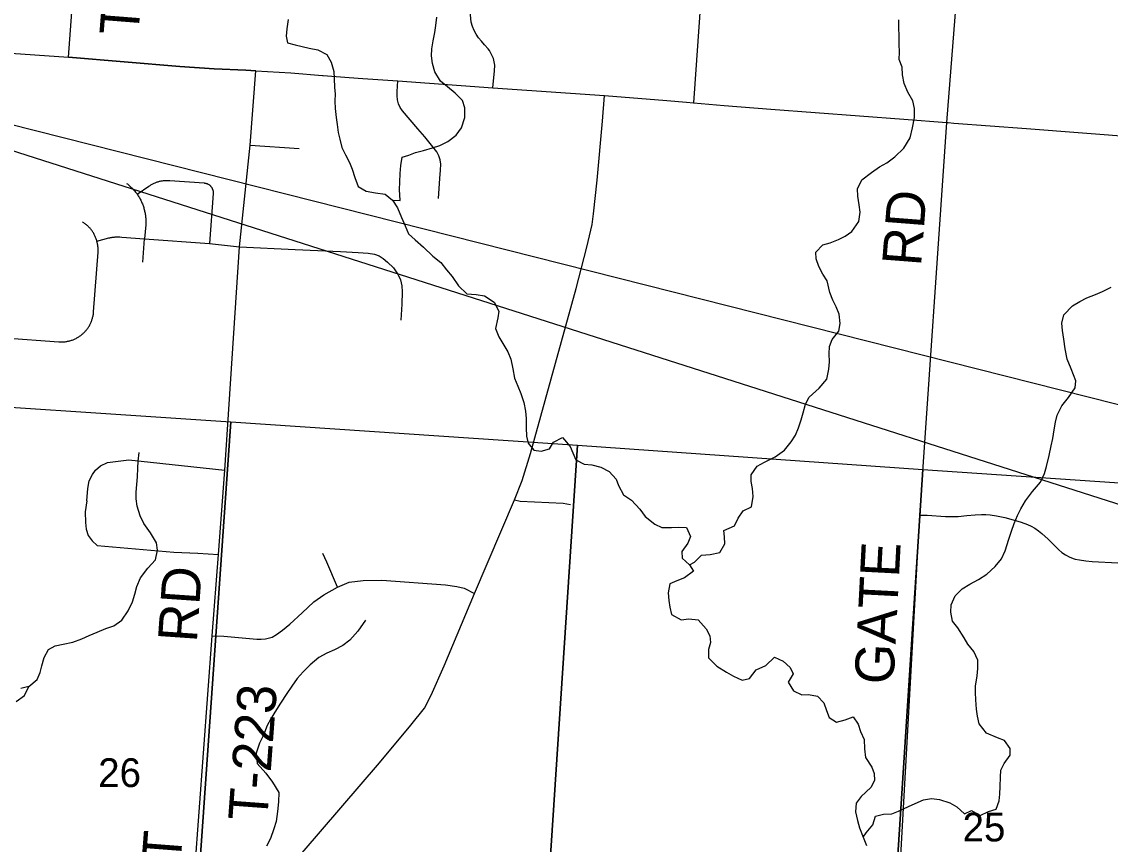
# Model space of a CAD drawing. Extents: x 0 to 34, y 0 to 22.
# Drawn here: x 6.46 to 8.044, y 16.406 to 17.603 of the extents above; entities that cross this region are included whole.
import ezdxf

# ---------------------------------------------------------------- set-up
doc = ezdxf.new("R2010")
doc.units = 0
for name, color, linetype in [('GM_X_Corporation', 7, 'Continuous'), ('GM_X_County_Road', 7, 'Continuous'), ('GM_X_Minor_Lake', 7, 'Continuous'), ('GM_X_Minor_River', 7, 'Continuous'), ('GM_X_Section_Text', 7, 'Continuous'), ('GM_X_State_Route', 7, 'Continuous'), ('GM_X_Township_Road', 7, 'Continuous'), ('GM_X_Township_Road_Text', 7, 'Continuous'), ('SH_Text', 7, 'Continuous')]:
    doc.layers.add(name, color=color, linetype=linetype)

msp = doc.modelspace()

# ---------------------------------------------------------------- linework, layer by layer
at = {"layer": 'GM_X_Corporation'}
for points in [[(6.2535, 17.0548), (6.7642, 17.0207), (6.6929, 16.0021), (6.1806, 16.0412)], [(6.7642, 17.0207), (7.2687, 16.9868), (7.2018, 15.9686), (6.6929, 16.0021)], [(7.2687, 16.9868), (7.7715, 16.9516), (7.7055, 15.9334), (7.2018, 15.9686)], [(7.7715, 16.9516), (8.2797, 16.9169), (8.2166, 15.8976), (7.7055, 15.9334)]]:
    msp.add_lwpolyline(points, close=True, dxfattribs=at)
at = {"layer": 'GM_X_County_Road'}
msp.add_lwpolyline([(6.556, 16.0261), (6.6991, 16.1965), (6.9804, 16.5242), (7.026, 16.579), (7.046, 16.6041), (7.0557, 16.6231), (7.0747, 16.6658), (7.119, 16.7711), (7.177, 16.9074), (7.1885, 16.9354), (7.2006, 16.9746), (7.2668, 17.2151), (7.2825, 17.2751), (7.2901, 17.3083), (7.2922, 17.3236), (7.2973, 17.373), (7.3052, 17.4586), (7.3081, 17.496)], dxfattribs=at)
at = {"layer": 'GM_X_Minor_Lake'}
msp.add_lwpolyline([(6.4518, 16.6138), (6.464, 16.6224), (6.4702, 16.6353), (6.4585, 16.6328)], dxfattribs=at)
at = {"layer": 'GM_X_Minor_River'}
for points in [[(6.8478, 17.6065), (6.8458, 17.5929), (6.8449, 17.5823), (6.8467, 17.5727), (6.858, 17.57), (6.8678, 17.5676), (6.878, 17.5648), (6.8909, 17.5624), (6.9037, 17.5558), (6.9104, 17.5447), (6.914, 17.531), (6.9147, 17.5208), (6.9153, 17.5079), (6.9159, 17.4984), (6.9158, 17.4877), (6.9161, 17.4771), (6.9175, 17.4642), (6.9189, 17.4539), (6.9206, 17.4421), (6.9228, 17.4323), (6.9257, 17.4205), (6.9313, 17.4098), (6.9368, 17.3983), (6.9409, 17.3888), (6.9449, 17.3766), (6.9497, 17.3636), (6.9614, 17.3567), (6.975, 17.3543), (6.9886, 17.3522), (6.9995, 17.3434), (7.0066, 17.3323), (7.0125, 17.3182), (7.018, 17.3064), (7.0228, 17.2946), (7.0326, 17.2861), (7.0446, 17.2753), (7.0581, 17.2623), (7.0697, 17.2527), (7.0783, 17.242), (7.0862, 17.2324), (7.0955, 17.219), (7.1079, 17.2071), (7.1211, 17.2062), (7.1332, 17.2042), (7.1475, 17.1953), (7.1542, 17.182), (7.153, 17.1725), (7.1494, 17.157), (7.1542, 17.1448), (7.1616, 17.1325), (7.1676, 17.1226), (7.1716, 17.1119), (7.1745, 17.0979), (7.177, 17.0846), (7.1818, 17.0727), (7.1863, 17.0621), (7.1907, 17.0491), (7.1932, 17.0362), (7.1942, 17.0259), (7.1941, 17.0119), (7.1947, 17.0001), (7.1968, 16.9898), (7.2054, 16.9795)], [(6.9995, 17.3434), (7.0105, 17.3433), (7.0099, 17.3592), (7.01, 17.3698), (7.0105, 17.3824), (7.0114, 17.3941), (7.0134, 17.4063), (7.0233, 17.4092), (7.0328, 17.4129), (7.0446, 17.4162), (7.0575, 17.4198), (7.0682, 17.4231), (7.08, 17.4291), (7.0922, 17.4381), (7.0999, 17.449), (7.105, 17.4641), (7.1048, 17.4782), (7.1015, 17.4889), (7.0906, 17.4996), (7.0797, 17.5088), (7.0692, 17.5169), (7.061, 17.5307), (7.0577, 17.5425), (7.0563, 17.5539), (7.0568, 17.5641), (7.0588, 17.5755), (7.0609, 17.588), (7.0625, 17.5982), (7.0641, 17.6103)], [(7.4321, 16.8128), (7.4393, 16.8165), (7.4493, 16.8267), (7.4618, 16.8277), (7.4758, 16.8306), (7.4832, 16.843), (7.4829, 16.8533), (7.4819, 16.8628), (7.4975, 16.8694), (7.5025, 16.8804), (7.5102, 16.8913), (7.522, 16.8973), (7.5244, 16.912), (7.5234, 16.9238), (7.5216, 16.9341), (7.5218, 16.9439), (7.5302, 16.9564), (7.5409, 16.9623), (7.5565, 16.9698), (7.5702, 16.9795), (7.5798, 16.9919), (7.586, 17.0017), (7.5903, 17.0123), (7.5942, 17.0237), (7.5973, 17.0339), (7.6005, 17.0464), (7.6063, 17.0569), (7.6205, 17.0697), (7.6316, 17.0829), (7.6348, 17.0976), (7.6357, 17.1083), (7.6354, 17.1197), (7.6355, 17.1307), (7.6394, 17.1409), (7.6494, 17.1529), (7.6514, 17.1639), (7.6497, 17.1776), (7.6452, 17.1883), (7.6404, 17.1978), (7.636, 17.2092), (7.6324, 17.226), (7.626, 17.2359), (7.6201, 17.247), (7.6164, 17.258), (7.6158, 17.2679), (7.6258, 17.2788), (7.6364, 17.2813), (7.6489, 17.2865), (7.6585, 17.291), (7.668, 17.2981), (7.6784, 17.3124), (7.6804, 17.3261), (7.6787, 17.3367), (7.6769, 17.3493), (7.6766, 17.3603), (7.6828, 17.3731), (7.6966, 17.384), (7.7084, 17.3922), (7.7191, 17.3978), (7.7309, 17.4068), (7.7439, 17.4195), (7.7532, 17.4346), (7.7564, 17.449), (7.7592, 17.4642), (7.7593, 17.4771), (7.7568, 17.4881), (7.7497, 17.5011), (7.7442, 17.5133), (7.7417, 17.5262), (7.7414, 17.5373), (7.737, 17.5483), (7.7375, 17.5593), (7.7372, 17.5707), (7.737, 17.5836), (7.7364, 17.5939), (7.7365, 17.6064)], [(7.6846, 16.4162), (7.6892, 16.4222), (7.6988, 16.4343), (7.7024, 16.4467), (7.7142, 16.4497), (7.7263, 16.4499), (7.7362, 16.454), (7.7506, 16.4607), (7.7602, 16.4651), (7.7727, 16.4707), (7.7841, 16.4725), (7.7958, 16.4708), (7.8109, 16.4661), (7.8211, 16.4603), (7.8324, 16.4503), (7.8423, 16.4548), (7.8551, 16.4478), (7.8669, 16.4534), (7.8783, 16.4571), (7.8826, 16.4692), (7.8838, 16.4786), (7.8843, 16.49), (7.8845, 16.5037), (7.8849, 16.5136), (7.89, 16.5234), (7.8988, 16.5354), (7.8985, 16.5453), (7.8903, 16.5571), (7.8801, 16.5607), (7.8643, 16.5677), (7.8535, 16.5811), (7.8509, 16.5921), (7.8495, 16.6027), (7.8485, 16.616), (7.8483, 16.6267), (7.8484, 16.6361), (7.8504, 16.6509), (7.8517, 16.6615), (7.8518, 16.6737), (7.8459, 16.6867), (7.8369, 16.697), (7.8317, 16.7065), (7.8224, 16.7207), (7.8149, 16.7306), (7.8124, 16.7436), (7.8129, 16.7546), (7.8184, 16.7674), (7.8287, 16.7779), (7.8401, 16.7843), (7.8527, 16.7913), (7.8645, 16.7992), (7.8768, 16.8104), (7.886, 16.8214), (7.8914, 16.8331), (7.8965, 16.8501), (7.9004, 16.8618), (7.9043, 16.8728), (7.9094, 16.8845), (7.914, 16.8943), (7.921, 16.906), (7.931, 16.9192), (7.9429, 16.9331), (7.9487, 16.9456), (7.9518, 16.9558), (7.9554, 16.9717), (7.9586, 16.9861), (7.961, 16.9967), (7.9626, 17.0092), (7.9647, 17.0202), (7.967, 17.0304), (7.974, 17.0444), (7.9836, 17.0561), (7.9932, 17.0704), (7.9941, 17.0806), (7.9875, 17.0982), (7.9816, 17.1123), (7.9787, 17.1271), (7.9766, 17.1412), (7.9748, 17.1541), (7.9738, 17.1643), (7.9769, 17.1765), (7.9892, 17.1896), (7.9999, 17.196), (8.0102, 17.2012), (8.0227, 17.2064), (8.033, 17.2108), (8.0456, 17.2171)], [(7.2054, 16.9795), (7.216, 16.9782), (7.2282, 16.9815), (7.234, 16.9913), (7.2469, 16.998), (7.2582, 16.985), (7.2618, 16.9755), (7.2663, 16.9656), (7.2787, 16.9594), (7.2897, 16.9581), (7.3029, 16.9549), (7.315, 16.9484), (7.3251, 16.9376), (7.3284, 16.9281), (7.3358, 16.9148), (7.3475, 16.9067), (7.3595, 16.8936), (7.3673, 16.8829), (7.3816, 16.8718), (7.3917, 16.8671), (7.4058, 16.867), (7.4156, 16.8676), (7.4277, 16.8671), (7.4333, 16.8541), (7.4294, 16.8443), (7.4205, 16.8319), (7.4212, 16.8224), (7.4321, 16.8128), (7.4377, 16.8032), (7.4247, 16.7939), (7.4133, 16.7895), (7.4034, 16.785), (7.4009, 16.7717), (7.4016, 16.7607), (7.403, 16.7512), (7.4059, 16.7402), (7.4198, 16.7328), (7.4308, 16.7342), (7.4445, 16.7326), (7.4561, 16.7195), (7.4613, 16.7092), (7.4623, 16.6997), (7.4595, 16.6895), (7.4594, 16.6774), (7.4718, 16.6651), (7.4857, 16.6562), (7.4959, 16.6504), (7.5083, 16.6446), (7.5193, 16.6472), (7.5289, 16.6596), (7.543, 16.6663), (7.5556, 16.6783), (7.5684, 16.6725), (7.5782, 16.6632), (7.5826, 16.6537), (7.5753, 16.642), (7.5835, 16.6294), (7.5956, 16.6236), (7.605, 16.6239), (7.6183, 16.6215), (7.6276, 16.6115), (7.6313, 16.6004), (7.6354, 16.5902), (7.6459, 16.5836), (7.6584, 16.5869), (7.6702, 16.5913), (7.6773, 16.5806), (7.681, 16.5699), (7.6862, 16.5585), (7.6864, 16.5445), (7.6882, 16.5323), (7.6975, 16.5182), (7.7008, 16.5086), (7.7014, 16.4984), (7.696, 16.4882), (7.6819, 16.4754), (7.6746, 16.4656), (7.6737, 16.4531), (7.6762, 16.4402), (7.6795, 16.4295), (7.6846, 16.4162), (7.6894, 16.404)], [(6.4702, 16.6353), (6.4821, 16.6458), (6.4864, 16.656), (6.4891, 16.6658), (6.4923, 16.6779), (6.4985, 16.6896), (6.5084, 16.6949), (6.5202, 16.697), (6.5342, 16.6999), (6.5471, 16.7051), (6.5578, 16.7099), (6.5696, 16.7147), (6.5821, 16.7199), (6.5936, 16.724), (6.6054, 16.7322), (6.6146, 16.7458), (6.6208, 16.759), (6.6244, 16.7699), (6.6271, 16.7813), (6.6329, 16.7938), (6.6433, 16.8077), (6.6544, 16.8201), (6.6572, 16.8341), (6.6558, 16.8448), (6.6473, 16.8593), (6.6376, 16.873), (6.6324, 16.8841), (6.6276, 16.8982), (6.6262, 16.9088), (6.6263, 16.9187), (6.6272, 16.9297), (6.6281, 16.9407), (6.6286, 16.9532), (6.6295, 16.9635), (6.6307, 16.9764)], [(6.96, 16.7319), (6.9488, 16.7161), (6.9373, 16.7029), (6.9274, 16.6951), (6.9152, 16.6891), (6.9041, 16.6839), (6.8923, 16.6776), (6.8797, 16.6671), (6.8697, 16.6569), (6.8609, 16.6472), (6.8529, 16.6359), (6.8455, 16.6253), (6.8367, 16.6114), (6.8282, 16.5982), (6.8224, 16.5884), (6.817, 16.5785), (6.8119, 16.5646), (6.8061, 16.5528), (6.801, 16.5385), (6.8024, 16.5233), (6.8151, 16.5091), (6.8248, 16.4961), (6.8338, 16.4812), (6.8336, 16.4675), (6.8323, 16.4535), (6.8303, 16.4391), (6.8267, 16.4281), (6.8217, 16.4142), (6.8159, 16.4032)]]:
    msp.add_lwpolyline(points, dxfattribs=at)
at = {"layer": 'GM_X_State_Route'}
for p, q in [((6.8986, 17.5251), (6.9365, 17.5223)), ((7.7438, 17.4615), (7.8067, 17.4568)), ((7.8067, 17.4568), (7.8086, 17.4566)), ((7.8086, 17.4566), (7.8165, 17.456))]:
    msp.add_line(p, q, dxfattribs=at)
for points in [[(5.9774, 17.5906), (5.9905, 17.5897), (6.0278, 17.587), (6.0741, 17.5836), (6.1651, 17.5775), (6.2475, 17.5714), (6.528, 17.552)], [(6.528, 17.552), (6.6901, 17.5382), (6.7397, 17.5351), (6.7862, 17.5328), (6.8004, 17.5319)], [(6.8004, 17.5319), (6.8513, 17.5289), (6.8976, 17.5252), (6.8986, 17.5251)], [(6.9365, 17.5223), (6.9565, 17.5209), (7.0075, 17.5176), (7.1456, 17.5072), (7.3081, 17.496)], [(7.3081, 17.496), (7.3987, 17.4886), (7.4277, 17.4861)], [(7.4277, 17.4861), (7.4377, 17.4852), (7.4823, 17.4816), (7.5504, 17.4761), (7.7438, 17.4615)], [(7.8165, 17.456), (7.9224, 17.4479), (8.1671, 17.4291), (8.3155, 17.4173), (8.4063, 17.4124), (8.5807, 17.4058), (8.7608, 17.3992), (8.8999, 17.39), (8.9, 17.39)]]:
    msp.add_lwpolyline(points, dxfattribs=at)
at = {"layer": 'GM_X_Township_Road'}
for p, q in [((6.7924, 17.4238), (6.8637, 17.4188)), ((6.6362, 17.2535), (6.6387, 17.2875))]:
    msp.add_line(p, q, dxfattribs=at)
for points in [[(6.528, 17.552), (6.5428, 17.755), (6.553, 17.872), (6.5547, 17.9434), (6.5622, 17.9715), (6.5676, 18.0635)], [(7.8067, 17.4568), (7.8439, 17.9308), (7.8449, 17.9659)], [(7.1387, 17.564), (7.1336, 17.5698), (7.1289, 17.5751), (7.1249, 17.58), (7.1213, 17.5852), (7.1184, 17.5908), (7.116, 17.5967), (7.1142, 17.6027), (7.1133, 17.6084), (7.1131, 17.6136), (7.1135, 17.6217), (7.1141, 17.6322), (7.1163, 17.662), (7.1202, 17.7086), (7.1252, 17.7731)], [(7.4527, 17.6997), (7.4377, 17.4852)], [(7.1456, 17.5072), (7.1482, 17.5322), (7.1484, 17.5401), (7.1463, 17.5499), (7.1406, 17.5618), (7.1387, 17.564)], [(6.8004, 17.5319), (6.7862, 17.5328), (6.7397, 17.5351), (6.6901, 17.5382), (6.528, 17.552)], [(6.6991, 16.1965), (6.737, 16.7093), (6.7461, 16.8276), (6.7553, 16.9507), (6.7768, 17.2757), (6.7924, 17.4238), (6.8004, 17.5319)], [(7.0667, 17.3463), (7.0686, 17.3752), (7.0695, 17.3871), (7.0697, 17.396), (7.0689, 17.4023), (7.067, 17.4083), (7.0656, 17.4112), (7.0641, 17.414), (7.0604, 17.4191), (7.0464, 17.4358), (7.0362, 17.4475), (7.0143, 17.4735), (7.0107, 17.4785), (7.008, 17.4838), (7.0066, 17.4896), (7.0062, 17.4957), (7.0063, 17.5019), (7.0075, 17.5176)], [(7.5902, 15.9401), (7.5965, 15.9796), (7.6036, 16.0079), (7.6181, 16.0362), (7.6409, 16.0588), (7.6848, 16.0992), (7.706, 16.125), (7.7171, 16.1497), (7.7242, 16.1769), (7.7323, 16.2582), (7.7673, 16.885), (7.8067, 17.4568)], [(6.6124, 17.3681), (6.6135, 17.3673), (6.6146, 17.3664), (6.6157, 17.3655), (6.6168, 17.3646), (6.6178, 17.3637), (6.6188, 17.3627), (6.6198, 17.3618), (6.6208, 17.3608), (6.6218, 17.3598), (6.6227, 17.3587), (6.6236, 17.3577), (6.6245, 17.3566), (6.6254, 17.3555), (6.6262, 17.3544), (6.6271, 17.3533), (6.6279, 17.3522), (6.6287, 17.351), (6.6295, 17.3498), (6.6302, 17.3486), (6.631, 17.3474), (6.6317, 17.3461), (6.6323, 17.3449), (6.633, 17.3436), (6.6336, 17.3423), (6.6342, 17.341), (6.6348, 17.3397), (6.6354, 17.3384), (6.6359, 17.337), (6.6364, 17.3357), (6.6368, 17.3343), (6.6373, 17.333), (6.6377, 17.3316), (6.6381, 17.3302), (6.6384, 17.3288), (6.6387, 17.3274), (6.639, 17.326), (6.6393, 17.3246), (6.6395, 17.3232), (6.6397, 17.3218), (6.6399, 17.3204), (6.64, 17.319), (6.6402, 17.3175), (6.6402, 17.3161), (6.6403, 17.3147), (6.6403, 17.3132), (6.6403, 17.3118), (6.6403, 17.3104), (6.6402, 17.309), (6.6402, 17.3075), (6.6387, 17.2875)], [(6.6279, 17.3522), (6.6447, 17.3639), (6.6457, 17.3646), (6.6466, 17.3652), (6.6476, 17.3658), (6.6486, 17.3664), (6.6496, 17.367), (6.6507, 17.3675), (6.6517, 17.368), (6.6527, 17.3685), (6.6538, 17.3689), (6.6549, 17.3694), (6.656, 17.3698), (6.6571, 17.3701), (6.6582, 17.3705), (6.6593, 17.3708), (6.6604, 17.3711), (6.6615, 17.3713), (6.6626, 17.3716), (6.6638, 17.3718), (6.6649, 17.372), (6.6661, 17.3721), (6.6672, 17.3723), (6.6684, 17.3724), (6.6695, 17.3724), (6.6707, 17.3725), (6.6718, 17.3725), (6.673, 17.3725), (6.6741, 17.3724), (6.6753, 17.3724), (6.7253, 17.3687), (6.7259, 17.3686), (6.7266, 17.3685), (6.7272, 17.3684), (6.7278, 17.3683), (6.7284, 17.3681), (6.729, 17.3679), (6.7296, 17.3677), (6.7302, 17.3674), (6.7308, 17.3671), (6.7314, 17.3668), (6.7319, 17.3665), (6.7324, 17.3661), (6.7329, 17.3658), (6.7334, 17.3654), (6.7339, 17.3649), (6.7344, 17.3645), (6.7348, 17.364), (6.7352, 17.3635), (6.7356, 17.363), (6.736, 17.3625), (6.7363, 17.362), (6.7367, 17.3614), (6.737, 17.3609), (6.7372, 17.3603), (6.7375, 17.3597), (6.7377, 17.3591), (6.7379, 17.3585), (6.7381, 17.3579), (6.7382, 17.3573), (6.7383, 17.3566), (6.7384, 17.356), (6.7384, 17.3554), (6.7385, 17.3547), (6.7385, 17.3541), (6.7384, 17.3535), (6.7331, 17.2805)], [(6.4347, 17.1431), (6.5137, 17.1373), (6.5148, 17.1372), (6.516, 17.1372), (6.5172, 17.1372), (6.5184, 17.1372), (6.5196, 17.1372), (6.5207, 17.1373), (6.5219, 17.1374), (6.5231, 17.1375), (6.5243, 17.1377), (6.5254, 17.1379), (6.5266, 17.1381), (6.5277, 17.1384), (6.5289, 17.1386), (6.53, 17.139), (6.5312, 17.1393), (6.5323, 17.1397), (6.5334, 17.14), (6.5345, 17.1405), (6.5356, 17.1409), (6.5367, 17.1414), (6.5377, 17.1419), (6.5388, 17.1424), (6.5398, 17.143), (6.5409, 17.1435), (6.5419, 17.1441), (6.5429, 17.1448), (6.5439, 17.1454), (6.5448, 17.1461), (6.5458, 17.1468), (6.5467, 17.1475), (6.5476, 17.1483), (6.5485, 17.1491), (6.5494, 17.1498), (6.5503, 17.1507), (6.5511, 17.1515), (6.5519, 17.1524), (6.5527, 17.1532), (6.5535, 17.1541), (6.5542, 17.155), (6.5549, 17.156), (6.5556, 17.1569), (6.5563, 17.1579), (6.557, 17.1589), (6.5576, 17.1599), (6.5582, 17.1609), (6.5588, 17.1619), (6.5593, 17.163), (6.5598, 17.164), (6.5603, 17.1651), (6.5608, 17.1662), (6.5612, 17.1673), (6.5617, 17.1684), (6.562, 17.1695), (6.5624, 17.1706), (6.5627, 17.1717), (6.563, 17.1729), (6.5633, 17.174), (6.5636, 17.1752), (6.5638, 17.1764), (6.564, 17.1775), (6.5641, 17.1787), (6.5643, 17.1799), (6.5644, 17.181), (6.5708, 17.268), (6.5708, 17.2691), (6.5709, 17.2703), (6.5709, 17.2714), (6.5709, 17.2726), (6.5708, 17.2737), (6.5708, 17.2749), (6.5707, 17.276), (6.5706, 17.2771), (6.5704, 17.2783), (6.5702, 17.2794), (6.57, 17.2805), (6.5698, 17.2816), (6.5695, 17.2827), (6.5693, 17.2839), (6.5689, 17.285), (6.5686, 17.2861), (6.5682, 17.2873), (6.5678, 17.2884), (6.5673, 17.2895), (6.5669, 17.2906), (6.5664, 17.2917), (6.5659, 17.2928), (6.5653, 17.2938), (6.5647, 17.2949), (6.5641, 17.2959), (6.5635, 17.2969), (6.5628, 17.2979), (6.5622, 17.2989), (6.5615, 17.2999), (6.5607, 17.3008), (6.56, 17.3017), (6.5592, 17.3027), (6.5584, 17.3035), (6.5576, 17.3044), (6.5567, 17.3053), (6.5559, 17.3061), (6.555, 17.3069), (6.5541, 17.3077), (6.5532, 17.3084), (6.5522, 17.3092), (6.5513, 17.3099), (6.5503, 17.3106), (6.5493, 17.3112), (6.5483, 17.3119)], [(6.5693, 17.2839), (6.5868, 17.2886), (6.5879, 17.2889), (6.589, 17.2891), (6.5902, 17.2894), (6.5913, 17.2896), (6.5924, 17.2898), (6.5935, 17.2899), (6.5947, 17.29), (6.5958, 17.2901), (6.597, 17.2902), (6.5981, 17.2902), (6.5992, 17.2902), (6.6004, 17.2902), (6.6015, 17.2902), (6.6027, 17.2901), (6.6056, 17.2899), (6.6387, 17.2875), (6.7331, 17.2805), (6.7768, 17.2757)], [(6.7768, 17.2757), (6.8579, 17.2718), (6.9236, 17.2687), (6.9497, 17.2674), (6.9642, 17.2666), (6.9735, 17.2651), (6.98, 17.2625), (6.9857, 17.2585), (6.9921, 17.2534), (7.0011, 17.245), (7.0078, 17.235), (7.011, 17.2278), (7.0133, 17.2189), (7.0134, 17.2102), (7.0129, 17.1923), (7.0117, 17.1691)], [(6.5543, 16.906), (6.5559, 16.9238), (6.5579, 16.9352), (6.5628, 16.9442), (6.567, 16.9503), (6.5743, 16.9567), (6.5845, 16.9616), (6.6158, 16.9657), (6.7553, 16.9507)], [(7.177, 16.9074), (7.1856, 16.9056), (7.2479, 16.9023), (7.2586, 16.9005)], [(6.5543, 16.906), (6.552, 16.89), (6.5527, 16.8745), (6.5534, 16.8646), (6.5564, 16.8555), (6.5621, 16.8475), (6.5697, 16.8406), (6.6813, 16.8311), (6.7163, 16.8298), (6.7461, 16.8276)], [(7.7673, 16.885), (7.7778, 16.8848), (7.8043, 16.8831), (7.8137, 16.8829), (7.823, 16.8832), (7.8354, 16.8843), (7.8478, 16.8857), (7.8571, 16.8861), (7.8633, 16.8859), (7.8695, 16.8854), (7.8787, 16.884), (7.8909, 16.8814), (7.903, 16.8784), (7.9149, 16.8748), (7.9237, 16.8715), (7.9293, 16.8689), (7.9348, 16.8659), (7.9399, 16.8624), (7.9447, 16.8584), (7.9538, 16.8499), (7.9693, 16.8346), (7.9741, 16.8306), (7.9793, 16.8272), (7.9848, 16.8243), (7.9905, 16.8219), (7.9935, 16.821), (7.9996, 16.8197), (8.0089, 16.8185), (8.0181, 16.8175), (8.0555, 16.8155)], [(6.9193, 16.7803), (6.9041, 16.8166), (6.8979, 16.829)], [(6.737, 16.7093), (6.7541, 16.7088), (6.802, 16.7045), (6.8083, 16.7045), (6.8148, 16.705), (6.8242, 16.7073), (6.8306, 16.7112), (6.8392, 16.7174), (6.8499, 16.7264), (6.8682, 16.743), (6.8848, 16.7589), (6.8996, 16.7689), (6.9193, 16.7803), (6.9366, 16.7872), (6.9569, 16.79), (6.9842, 16.7903), (7.0767, 16.7837), (7.0933, 16.781), (7.1037, 16.7786), (7.119, 16.7711)]]:
    msp.add_lwpolyline(points, dxfattribs=at)
at = {"layer": 'SH_Text'}
msp.add_lwpolyline([(9.625, 16.6492), (9.625, 16.3992), (5.875, 17.598)], close=True, dxfattribs=at)

# ---------------------------------------------------------------- texts
at = {"layer": 'GM_X_Section_Text'}
for s, p in [('26', (6.5711, 16.4891)), ('25', (7.8294, 16.4099))]:
    msp.add_text(s, height=0.04186, rotation=0, dxfattribs=at).set_placement(p)
at = {"layer": 'GM_X_Township_Road_Text'}
for s, rotation, p in [('T-223', 85.4937, (6.6294, 17.5821)), ('RD', 85.564, (7.7688, 17.2466)), ('GATE', 87.0397, (7.7287, 16.6377)), ('RD', 86.0533, (6.7146, 16.6989)), ('T-223', 85.7741, (6.8169, 16.4385)), ('AULT', 85.6205, (6.6796, 16.2291))]:
    msp.add_text(s, height=0.05682, rotation=rotation, dxfattribs=at).set_placement(p)

doc.saveas('drawing.dxf')
